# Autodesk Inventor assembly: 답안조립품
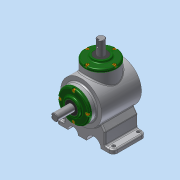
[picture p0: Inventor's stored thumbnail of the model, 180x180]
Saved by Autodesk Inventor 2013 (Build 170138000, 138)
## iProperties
Created: 2018-08
Part Number: 답안조립품
Document SubType Name: Assembly
Designer: Administrator
Author: Administrator
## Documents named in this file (14)
- C:\Users\Administrator\Desktop\480808V1027\답안조립품.iam
- C:\Users\Administrator\Desktop\480808V1027\본체.ipt
- C:\Users\Administrator\Desktop\480808V1027\메인 베벨기어.ipt
- C:\Users\Administrator\Desktop\480808V1027\메인 축.ipt
- 메인 축.ipt
- C:\Users\Administrator\Desktop\480808V1027\베어링 6203.ipt
- C:\Users\Administrator\Desktop\480808V1027\볼트 M4.ipt
- C:\Users\Administrator\Desktop\480808V1027\서브 베벨기어.ipt
- C:\Users\Administrator\Desktop\480808V1027\서브 축.ipt
- 서브 축.ipt
- C:\Users\Administrator\Desktop\480808V1027\오일실 17 32 8.ipt
- C:\Users\Administrator\Desktop\480808V1027\커버.ipt
- C:\Users\Administrator\Desktop\480808V1027\키 4x4.ipt
- C:\Users\Administrator\Desktop\480808V1027\키 5x5.ipt
